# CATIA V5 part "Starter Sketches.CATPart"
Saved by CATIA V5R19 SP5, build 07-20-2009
Part number: Starter Sketches
Bounding box of the stored display mesh (mm): x -2751.913 to 38639.977, y -3048 to 24319.59, z 0 to 0
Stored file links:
  D:\Work\2009-03-18 GT Knowledge SVN\GT.KNOWLEDGE\Training\Work\2009-T02.GettingStarted\Models\Starter Sketches.CATPart
  D:\Work\2009-03-18 GT Knowledge SVN\GT.KNOWLEDGE\Training\Work\2009-T02.GettingStarted\Models\My First Digital Project.CATPart
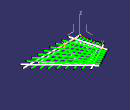
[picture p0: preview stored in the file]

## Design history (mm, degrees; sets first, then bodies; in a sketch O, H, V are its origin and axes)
Set1 "Sketches to Copy"
  AxisSystem1: origin (0, 0, 0), X (1, 0, 0), Y (0, 1, 0), Z (0, 0, 1)
  Sketch1 "Partitions" on xy-plane, origin (0, 0, 0), H (1, 0, 0), V (0, 1, 0)
    projected line E1 (34424.4022, 0) -> (3944.4022, 0)
    projected line E2 (0, 14720.7096) -> (3944.4022, 0)
    projected line E3 (0, 14720.7096) -> (13368.4042, 22038.0431)
    projected line E4 (34424.4022, 0) -> (13368.4042, 22038.0431)
    construction line L1 (0, 14720.7096) -> (34424.4022, 0)
    line L2 (8325.3671, 1828.8) -> (4962.35, 3266.9077)
    point P9 (4962.35, 3266.9077)
    line L3 (4962.35, 3266.9077) -> (4880.5472, 8987.1813)
    point P10 (4880.5472, 8987.1813)
    line L4 (4880.5472, 8987.1813) -> (7517.078, 15152.7126)
    point P11 (7517.078, 15152.7126)
    line L5 (7517.078, 15152.7126) -> (11709.5345, 19045.2091)
    point P12 (11709.5345, 19045.2091)
    line L6 (11709.5345, 19045.2091) -> (15072.5516, 17607.1014)
    point P13 (8325.3671, 1828.8)
    point P14 (15072.5516, 17607.1014)
    point P15 (6198.8126, 12069.9469)
    point P16 (13968.8059, 8084.3115)
    point P17 (13390.1652, 7011.1742)
    point P18 (12719.1739, 5993.2256)
    point P19 (11964.8857, 5035.3645)
    point P20 (14448.1752, 9205.3172)
    point P21 (14824.3558, 10365.0312)
    point P22 (15096.8362, 11553.3927)
    point P23 (15268.3289, 12760.4714)
    line L7 (2138.3258, 13806.3096) -> (5347.6898, 1828.8)
    line L8 (5347.6898, 1828.8) -> (30147.7506, 1828.8)
    line L9 (30147.7506, 1828.8) -> (13015.5317, 19760.0601)
    line L10 (13015.5317, 19760.0601) -> (2138.3258, 13806.3096)
    spline S1 through (8325.3671, 1828.8) (14221.2222, 8639.3699) (15072.5516, 17607.1014)
    construction line L11 (15072.5516, 17607.1014) -> (8325.3671, 1828.8)
    construction line L12 (11709.5345, 19045.2091) -> (4962.35, 3266.9077)
    construction spline S2 through (11709.5345, 19045.2091) (5813.6795, 12234.6392) (4962.35, 3266.9077)
    construction line L13 (13391.0431, 18326.1553) -> (6643.8586, 2547.8539)
    point P28 (13391.0431, 18326.1553)
    point P29 (6643.8586, 2547.8539)
    point P30 (8325.3671, 1828.8)
    point P31 (14221.2222, 8639.3699)
    point P32 (15072.5516, 17607.1014)
    point P33 (11709.5345, 19045.2091)
    point P34 (5813.6795, 12234.6392)
    point P35 (4962.35, 3266.9077)
    length L4 = 6705.6
    distance L1 P16 = 609.6
    distance P16 P17 = 1219.2
    distance P17 P18 = 1219.2
    distance P18 P19 = 1219.2
    length L6 = 3657.6
    distance P31 L11 = 2743.2
    distance L12 P34 = 2743.2
    distance L8 E1 = 1828.8
    distance L7 E2 = 1828.8
    parallelism: L6 L1
    midpoint: P15 L4, P28 L6, P29 L2
    coincidence: P16 S1, P17 S1, P18 S1, P19 S1, L8 P13, L7 P9, P12 L10, L9 P14, P30 P13, P31 L1, P32 P14, P33 P12, P34 L1, P35 P9, P15 L1, P11 S2, P10 S2
    symmetry: P16 P20 L1, P17 P21 L1, P18 P22 L1, P19 P23 L1, L2 L6 L1, L7 L10 L1, L8 L9 L1
  Sketch2 "Grid" on xy-plane, origin (0, 0, 0), H (1, 0, 0), V (0, 1, 0)
    projected line E1 (34424.4022, 0) -> (3944.4022, 0)
    projected line E2 (34424.4022, 0) -> (13368.4042, 22038.0431)
    point P3 (34424.4022, 0)
    projected line E3 (0, 14720.7096) -> (13368.4042, 22038.0431)
    point P5 (0, 14720.7096)
    point P6 (13368.4042, 22038.0431)
    projected line E4 (0, 14720.7096) -> (3944.4022, 0)
    point P7 (0, 14720.7096)
    point P8 (3944.4022, 0)
    point P9 (493.0503, 12880.6209)
    point P10 (986.1006, 11040.5322)
    point P11 (1479.1508, 9200.4435)
    point P12 (1972.2011, 7360.3548)
    point P13 (2465.2514, 5520.2661)
    point P14 (2958.3017, 3680.1774)
    point P15 (3451.352, 1840.0887)
    point P16 (31792.4025, 2754.7554)
    point P17 (29160.4027, 5509.5108)
    point P18 (26528.403, 8264.2662)
    point P19 (23896.4032, 11019.0216)
    point P20 (21264.4034, 13773.777)
    point P21 (18632.4037, 16528.5323)
    point P22 (16000.4039, 19283.2877)
    point P23 (23896.4032, 11019.0216)
    construction line L1 (34424.4022, 0) -> (0, 14720.7096)
    offset line E5 (36628.2066, 2105.5998) -> (15572.2085, 24143.6429)
    offset line E6 (38639.978, 0) -> (15572.2085, 24143.6429)
    line L2 (35881.8776, 2886.7373) -> (322.8841, 1739.1219)
    point P26 (35881.8776, 2886.7373)
    line L3 (33112.3623, 5785.4219) -> (-139.2731, 3463.9162)
    point P27 (33112.3623, 5785.4219)
    line L4 (30329.8087, 8697.7529) -> (-596.7117, 5171.1004)
    point P28 (30329.8087, 8697.7529)
    line L5 (27532.2702, 11625.7677) -> (-1048.2612, 6856.3061)
    point P29 (27532.2702, 11625.7677)
    line L6 (24717.3924, 14571.9305) -> (-1492.3291, 8513.5901)
    point P30 (24717.3924, 14571.9305)
    line L7 (21882.3005, 17539.2502) -> (-1926.6918, 10134.6538)
    point P31 (21882.3005, 17539.2502)
    line L8 (19023.4469, 20531.4399) -> (-2348.1478, 11707.5487)
    point P32 (19023.4469, 20531.4399)
    point P33 (-2348.1478, 11707.5487)
    reference offset line E7 (-2944.1419, 13931.8291) -> (1000.2603, -788.8804)
    point P36 (-2348.1478, 11707.5487)
    point P37 (-1926.6918, 10134.6538)
    point P38 (-1492.3291, 8513.5901)
    point P39 (-1048.2612, 6856.3061)
    point P40 (-596.7117, 5171.1004)
    point P41 (-139.2731, 3463.9162)
    point P42 (322.8841, 1739.1219)
    point P43 (556.4821, 18500.0302)
    point P44 (8940.3063, -3048)
    line L9 (8940.3063, -3048) -> (556.4821, 18500.0302)
    point P45 (1984.8844, 19281.8809)
    point P46 (13078.6928, -3048)
    line L10 (13078.6928, -3048) -> (1984.8844, 19281.8809)
    point P47 (3457.0305, 20087.6752)
    point P48 (17182.6826, -3048)
    line L11 (17182.6826, -3048) -> (3457.0305, 20087.6752)
    point P49 (4962.0694, 20911.4737)
    point P50 (21257.4111, -3048)
    line L12 (21257.4111, -3048) -> (4962.0694, 20911.4737)
    point P51 (6492.4652, 21749.1516)
    point P52 (25307.0398, -3048)
    line L13 (25307.0398, -3048) -> (6492.4652, 21749.1516)
    point P53 (8042.8203, 22597.7544)
    point P54 (29334.9768, -3048)
    line L14 (29334.9768, -3048) -> (8042.8203, 22597.7544)
    point P55 (9609.1679, 23455.1109)
    point P56 (33344.0399, -3048)
    line L15 (33344.0399, -3048) -> (9609.1679, 23455.1109)
    line L16 (38639.978, 0) -> (788.8804, 0)
    point P57 (38639.978, 0)
    point P58 (788.8804, 0)
    line L17 (16136.4022, 23553.1353) -> (-2751.9132, 13214.4216)
    point P59 (-2751.9132, 13214.4216)
    point P60 (16136.4022, 23553.1353)
    point P61 (-811.9632, 17750.9976)
    point P62 (4761.1114, -3048)
    line L18 (4761.1114, -3048) -> (-811.9632, 17750.9976)
    point P63 (11188.5268, 24319.5892)
    point P64 (37336.5792, -3048)
    line L19 (37336.5792, -3048) -> (11188.5268, 24319.5892)
    distance P7 P9 = 1905 {= Sketch2.length(E4) /8}
    distance P9 P10 = 1905 {= Sketch2.distance(P7 P9)}
    distance P10 P11 = 1905 {= Sketch2.distance(P7 P9)}
    distance P11 P12 = 1905 {= Sketch2.distance(P7 P9)}
    distance P12 P13 = 1905 {= Sketch2.distance(P7 P9)}
    distance P13 P14 = 1905 {= Sketch2.distance(P7 P9)}
    distance P14 P15 = 1905 {= Sketch2.distance(P7 P9)}
    distance P3 P16 = 3810 {= Sketch2.length(E2) /8}
    distance P16 P17 = 3810 {= Sketch2.distance(P3 P16)}
    distance P17 P18 = 3810 {= Sketch2.distance(P3 P16)}
    distance P18 P19 = 3810 {= Sketch2.distance(P3 P16)}
    distance P19 P20 = 3810 {= Sketch2.distance(P3 P16)}
    distance P20 P21 = 3810 {= Sketch2.distance(P3 P16)}
    distance P21 P22 = 3810 {= Sketch2.distance(P3 P16)}
    length E4 = 15240 (reference)
    length E2 = 30480 (reference)
    coincidence: E4 P9, E4 P10, E4 P11, E4 P12, E4 P13, E4 P14, E4 P15, E2 P16, E2 P17, E2 P18, E2 P19, E2 P20, E2 P21, E2 P22, P23 E2, P26 E5, P15 L2, P16 L2, P27 E5, P14 L3, P17 L3, P28 E5, P18 L4, P13 L4, P29 E5, P30 E5, P31 E5, P32 E5, L8 P9, P19 L5, P12 L5, P20 L6, P11 L6, P21 L7, P10 L7, P22 L8, E7 P36, E7 P37, E7 P38, E7 P39, E7 P40, E7 P41, E7 P42, P3 L16, P8 L16, E7 P58, P6 L17, P5 L17, E7 P59, E5 P60
    symmetry: P36 P43 L1, P32 P44 L1, L8 L9 L1, P37 P45 L1, P31 P46 L1, L7 L10 L1, P38 P47 L1, P30 P48 L1, L6 L11 L1, P39 P49 L1, P29 P50 L1, L5 L12 L1, P40 P51 L1, P28 P52 L1, L4 L13 L1, P41 P53 L1, P27 P54 L1, L3 L14 L1, P42 P55 L1, P26 P56 L1, L2 L15 L1, P59 P61 L1, P60 P62 L1, L17 L18 L1, P58 P63 L1, P57 P64 L1, L16 L19 L1
    horizontal: L16 H
Body1 (main body)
